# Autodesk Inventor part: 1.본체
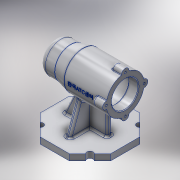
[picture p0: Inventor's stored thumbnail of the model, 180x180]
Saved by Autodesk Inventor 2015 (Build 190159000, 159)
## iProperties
Created: 2019-12
Part Number: 1.본체
Material: 알루미늄 6061
Document SubType Name: Modeling
Designer: SCD-A02
Density: 2.7 g/cm^3
Appearance: 알루미늄 - 평지
Mass: 725.606 g
Surface Area: 715.209 cm^2
Volume: 268.743 cm^3
Author: SCD-A02
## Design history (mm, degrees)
sketch "스케치1"
  geometry: L1 (0, 0)-(0, 25); L2 (0, 25)-(25, 25); L3 (25, 25)-(45, 30); L4 (45, 30)-(112, 30); L5 (112, 30)-(112, 0); L6 (112, 0)-(0, 0)
  constraints: 12 end point, 2 perpendicular, 2 vertical, 1 parallel
  dimensions: "d0" = 50 diameter of L2 L6; "d1" = 60 diameter of L4 L6; "d2" = 25 distance of L1.end L2.end; "d3" = 45 horizontal distance of L1.end L3.end; "d4" = 112 distance between parallel lines of L1 L5
revolve "회전1" sketch "스케치1" stored, may be unused: angle "d5" = 90 deg
sketch "스케치2"
  geometry: L1 (6, 0)-(9, 0); L2 (9, 0)-(9, 10.5); L3 (9, 10.5)-(6, 10.5); L4 (6, 10.5)-(6, 0); L5 (9, 0)-(13, 0); L6 (13, 0)-(13, 16); L7 (13, 16)-(9, 16); L8 (9, 16)-(9, 0); L9 (13, 0)-(31, 0); L10 (31, 0)-(31, 17.5); L11 (31, 17.5)-(13, 17.5); L12 (13, 17.5)-(13, 0); L13 (31, 0)-(43, 0); L14 (43, 0)-(43, 21); L15 (43, 21)-(31, 21); L16 (31, 21)-(31, 0); L17 (43, 0)-(97, 0); L18 (97, 0)-(97, 24); L19 (97, 24)-(43, 24); L20 (43, 24)-(43, 0); L21 (112, -30)-(112, 30) reference; L22 (97, 0)-(112, 0); L23 (112, 0)-(112, 21); L24 (112, 21)-(97, 21); L25 (97, 21)-(97, 0); 1 further point
  constraints: 48 end point, 12 parallel, 6 horizontal, 6 perpendicular, 1 point on line
  dimensions: "d6" = 0 vertical distance of point (0, 0) L1.start; "d7" = 3 distance of L2.end L3.end; "d8" = 4 distance of L6.end L7.end; "d9" = 18 distance of L10.end L11.end; "d10" = 12 distance of L14.end L15.end; "d11" = 42 diameter of L15 L13; "d12" = 48 diameter of L19 L17; "d13" = 15 distance between parallel lines of L23 L25; "d14" = 54 distance between parallel lines of L25 L14; "d15" = 42 diameter of L24 L22; "d16" = 35 diameter of L11 L9; "d17" = 21 diameter of L3 L1; "d18" = 32 diameter of L7 L5
revolve "회전2" stored, may be unused: angle "d19" = 90 deg
node "작업 평면1"
sketch "스케치3"
  geometry: L1 (56, 0)-(5.263, 50.737); L2 (56, 0)-(0, 0); L3 (16.402, 39.598)-(0, 23.196); L4 (0, 23.196)-(16.402, 39.598); L5 (16.402, 39.598)-(32.804, 56); L6 (56, 56)-(32.804, 56); L7 (0, 0)-(0, 23.196); L8 (56, 0)-(95.901, 39.901); L9 (112, 0)-(112, 23.196); L10 (56, 56)-(79.196, 56); L11 (95.598, 39.598)-(79.196, 56); L12 (95.598, 39.598)-(112, 23.196); L13 (0, 0)-(0, -23.196); L14 (16.402, -39.598)-(0, -23.196); L15 (16.402, -39.598)-(32.804, -56); L16 (56, -56)-(32.804, -56); L17 (56, -56)-(79.196, -56); L18 (95.598, -39.598)-(79.196, -56); L19 (95.598, -39.598)-(112, -23.196); L20 (112, 0)-(112, -23.196); A1 r 56 centre (56, 0) between (16.402, 39.598) and (0, 0)
  constraints: 40 end point, 7 symmetric about line, 6 tangent, 3 horizontal, 3 point on line, 2 perpendicular, 2 point on circle, 2 vertical, 1 centre point, 1 collinear
  dimensions: "d21" = 56 distance of L1.start L2.end; "d22" = 112 diameter of A1; "d23" = 45 deg angle of L1 L2; "d24" = 45 deg angle of L8 L2
extrude "돌출1" join sketch "스케치3" distance "d25" = 10; taper "d26" = 0 deg
sketch "스케치4"
  geometry: L1 (-32.804, -70)-(0, -70) reference; L2 (-18, -70)-(-40.099, -22.609); L3 (-40.099, -22.609)-(-87, -22.609); L4 (-112, -70)-(-79.196, -70) reference; L5 (-79.196, -70)-(-32.804, -70) reference; L6 (0, -80)-(0, -70) reference; L7 (-87, -22.609)-(-87, -70); L8 (-18, -70)-(-87, -70); L9 (-112, -80)-(-112, -70) reference; 1 further point
  constraints: 8 end point, 1 collinear, 1 horizontal, 1 point on line, 1 vertical
  dimensions: "d27" = 18 distance from line of L2.start L6; "d28" = 25 distance between parallel lines of L7 L9; "d62" = 115 deg angle of L2 L1
extrude "돌출2" join sketch "스케치4" stored distance "d29" = 8; taper "d30" = 0 deg
node "작업 평면2"
sketch "스케치5"
  geometry: L1 (70, -36)-(0, -10.522); L2 (0, -10.522)-(0, 0); L3 (0, 0)-(70, 0); L4 (27.875, -4)-(70, -4) reference; L5 (70, 0)-(70, -36); L6 (70, -56)-(70, -23.196) reference; L7 (80, -56)-(70, -56) reference; L8 (70, 36)-(0, 10.522); L9 (0, 10.522)-(0, 0); L10 (27.875, 4)-(70, 4); L11 (70, 0)-(70, 36); 1 further point
  constraints: 16 end point, 5 symmetric about line, 1 parallel, 1 perpendicular, 1 vertical
  dimensions: "d32" = 0 distance between parallel lines of L5 L6; "d33" = 20 distance from line of L1.start L7; "d34" = 110 deg angle of L1 L6
extrude "돌출3" join sketch "스케치5" stored distance "d35" = 8; taper "d36" = 0 deg
revolve "회전3" stored, may be unused: angle "d37" = 90 deg
sketch "스케치6"
  geometry: C1 r 21 at (0, 0) reference; C2 r 6 at (-30, 0); A1 r 30 centre (0, 0) between (29.732, 4) and (29.732, -4) reference; A2 r 30 centre (0, 0) between (29.732, 4) and (29.732, -4) reference
  constraints: 2 point on circle, 1 centre point, 1 horizontal alignment
  dimensions: "d38" = 12 diameter of C2
extrude "돌출4" join sketch "스케치6" distance "d39" = 16; taper "d40" = 0 deg
fillet "모깎기1" dims "d41" = 3
fillet "모깎기2" dims "d42" = 1
sketch "스케치7"
  geometry: A1 r 6 centre (0, 0) between (-0.171, 5.998) and (-0.171, -5.998) reference
hole "구멍1" sketch "스케치7" at (0, 0) diameter "d43" = 3.242; stored, may be unused: countersink angle "d47" = 90 deg, drill point angle "d49" = 118 deg; dims "d44" = 8, "d45" = 4, "d46" = 2, "d48" = 11
sketch "스케치8"
  geometry: L1 (32.804, 56)-(0, 23.196) reference; C1 r 5 at (16.402, 39.598); 1 further point
  constraints: 1 centre point, 1 midpoint
  dimensions: "d53" = 10 diameter of C1
extrude "돌출5" cut sketch "스케치8" stored distance "d54" = 16; taper "d55" = 0 deg
fillet "모깎기3" dims "d56" = 10, "d57" = 3, "d58" = 0.3
chamfer "모따기1" distance "d59" = 1; stored, may be unused: second distance "d60" = 2, angle "d61" = 45 deg
fillet "모깎기4" dims "d63" = 3
node "작업 평면3"
sketch "스케치9"
  geometry: L1 (33.5, 29.226)-(33.5, 6.771) reference; 2 further points
  constraints: 1 horizontal alignment, 1 other
  dimensions: "d64" = 41 distance from line of point (-7.5, 0) L1
feature "엠보싱2" sketch "스케치9" dims "d67" = 0.5, "d68" = 0
node "솔리드1"
pattern_circular "원형 패턴1" dims "d51" = 360 deg
mirror "대칭1"
mirror "대칭2"
other parameters: "d31" = -56
